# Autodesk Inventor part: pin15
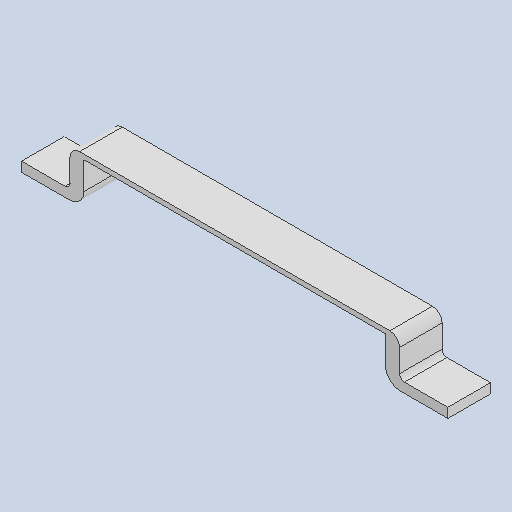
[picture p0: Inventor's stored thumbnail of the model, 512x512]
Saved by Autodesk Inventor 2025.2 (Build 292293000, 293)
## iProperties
Created: 2025-04
Part Number: pin15
Material: Generic
Description: PART--DESC
Document SubType Name: Modeling
Designer: BennF
Density: 1 g/cm^3
Appearance: Default
Author: BennF
Revision Number: NONE
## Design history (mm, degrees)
feature "Solid"
body "Solid1"
